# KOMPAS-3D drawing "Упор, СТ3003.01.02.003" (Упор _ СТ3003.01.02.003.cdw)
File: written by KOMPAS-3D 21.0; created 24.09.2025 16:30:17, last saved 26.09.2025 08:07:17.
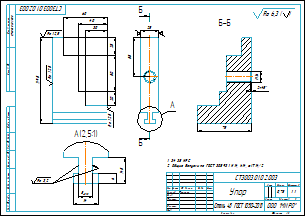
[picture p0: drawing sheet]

Sheet 1: A3, landscape

Document properties: Знак неуказанной шероховатости: 4; Параметр неуказанной шероховатости: Ra 6,3; Масса: 0.784266

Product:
- Part/product: Упор  | designation СТ3003.01.02.003
    Материал: Сталь 45  ГОСТ 1050-2013 (density 7810 kg/m3)
    Масса: 0.784266
    Форматы листов документа: A3

Title block, sheet 1: Наименование: Упор; designation: СТ3003.01.02.003; Материал: Сталь 45  ГОСТ 1050-2013; Масса: 0,78; Количество листов документа: 1; organisation: ООО "МИРО"; Форматы листов документа: A3; stored path: C:\Users\1\Yandex.Disk\Документы\Новая папка\Стапель №2\Стапель _ СТ3003.00.00.000\Опора _ СТ3003.01.00.000\2D\Кронштейн _ СТ3003.01.02.000\Упор _ СТ3003.01.02.003.cdw; Разработал: Тимонин

Views: Вид 1, Спереди, Проекционный вид 2, Разрез А-А, Выносной элемент 4, Разрез Б-Б, Выносной элемент А, Выносной элемент
Referenced files in C:\Users\1\Yandex.Disk\Документы\Новая папка\Стапель №2\Стапель _ СТ3003.00.00.000\Опора _ СТ3003.01.00.000\3D\Кронштейн _ СТ3003.01.02.000\: Упор _ СТ3003.01.02.003.m3d
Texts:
  Ra 12,5
  Ra 3,2
  Ra 6,3
  Ra 6,3 ( )
  Стили документа
  СТ3003.01.02.000
  СТ3003.01.02.003 Упор
Dimensions and other numbers on the sheet: 30; 40; 60; 20; 50; 25; 119,5; 55; 16; 2; 75; 8; 14; 14,5; 6; 1:1; 1; 0,78

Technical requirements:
  34...38 HRC.
  Общие допуски по ГОСТ 30893.1: Н14, h14, ± IT14/2.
